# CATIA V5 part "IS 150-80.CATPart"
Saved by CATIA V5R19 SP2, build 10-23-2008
Part number: IS 150-80
Bounding box of the stored display mesh (mm): x -15.868 to 15.868, y -15.868 to 15.868, z 0 to 210
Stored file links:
  C:\Users\Bora\Desktop\3D Katı model\IS serisi\IS 150\IS 150-80.CATPart
  C:\Program Files\Dassault Systemes\B19\intel_a\reffiles\standard\MetricThickPitch.txt
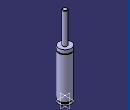
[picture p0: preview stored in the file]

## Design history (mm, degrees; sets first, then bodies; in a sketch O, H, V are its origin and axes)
Body1 (main body)
  Sketch1 on yz-plane, origin (0, 0, 0), H (0, 1, 0), V (0, 0, 1)
    point P3 (6, 209)
    point P5 (6, 209)
    point P7 (16, 118.5)
    point P8 (16, 116.5)
    point P12 (16, 116.5)
    point P13 (16, 118.5)
    line L1 (16, 0) -> (16, 4)
    line L2 (6, 209) -> (6, 128)
    arc A1 centre (5, 209) radius 1 from (6, 209) to (5, 210) ccw
    arc A2 centre (16, 117.5) radius 1 from (16, 118.5) to (16, 116.5) ccw
    line L3 (13.5, 7.5) -> (13.5, 4)
    line L4 (16, 7.5) -> (16, 116.5)
    line L5 (16, 118.5) -> (16, 128)
    line L6 (0, 0) -> (16, 0)
    line L7 (13.5, 4) -> (16, 4)
    line L8 (13.5, 7.5) -> (16, 7.5)
    line L9 (6, 128) -> (16, 128)
    line L10 (5, 210) -> (0, 210)
    point P15 (0, 210)
    horizontal: L6 H, L7 H, L8 H, L9 H
    tangency: L10 A1
    coincidence: P15 V, P3 P5, P7 P13, P8 P12
  Shaft1: profile Sketch1, axis Sketch1.V, angle 360
  Sketch2 on face of Shaft1 from Sketch1.L6, origin (0, 0, 0), H (1, 0, 0), V (0, -1, 0)
    point P1 (0, 0)
  Hole1: placed by Sketch2, at (0, 0, 0) direction (0, 0, 1), diameter 6.647, depth 7, threaded "M8", thread diameter 8, thread depth 7, pitch 1.25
